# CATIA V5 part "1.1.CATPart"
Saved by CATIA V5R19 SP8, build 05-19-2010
Part number: 1.1
Definition: NONE
Nomenclature: 1
Source: Unknown
Description: PART-1-DESC
Bounding box of the stored display mesh (mm): x -26.5 to 26.5, y 0 to 33, z -26.5 to 26.5
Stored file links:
  G:\EU_thinkMotion\CFAO_2010\SIL_groupe1\SIL_groupe1\A reprendre\fbruguiere\fbruguiere\fbruguiere\1.1.CATPart
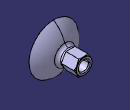
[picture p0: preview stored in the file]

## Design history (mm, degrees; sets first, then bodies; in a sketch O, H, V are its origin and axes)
Body1 "1" (main body)
  Solid1: solid without history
